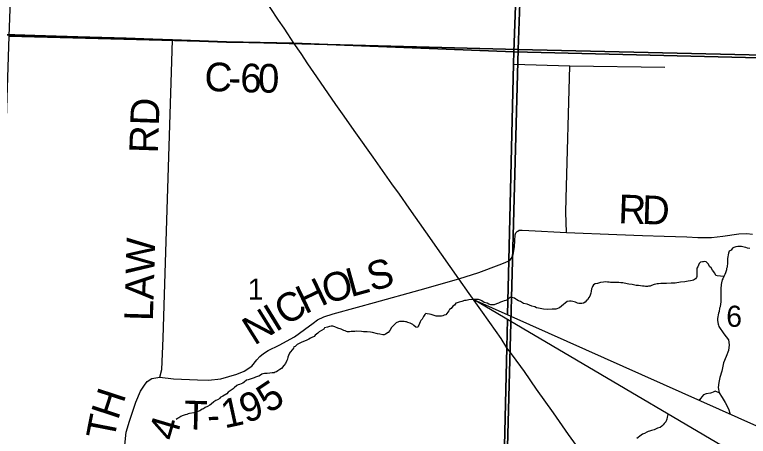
# Model space of a CAD drawing. Extents: x 0 to 34, y 0 to 22.
# Drawn here: x 4.391 to 5.846, y 16.765 to 17.601 of the extents above; entities that cross this region are included whole.
import ezdxf

# ---------------------------------------------------------------- set-up
doc = ezdxf.new("R2010")
doc.units = 0
for name, color, linetype in [('Default', 7, 'Continuous'), ('GM_X_County_Road', 7, 'Continuous'), ('GM_X_County_Road_Text', 7, 'Continuous'), ('GM_X_Minor_River', 7, 'Continuous'), ('GM_X_Section', 7, 'Continuous'), ('GM_X_Section_Text', 7, 'Continuous'), ('GM_X_Township_Road', 7, 'Continuous'), ('GM_X_Township_Road_Text', 7, 'Continuous'), ('GM_X_US_Route', 7, 'Continuous'), ('SH_Text', 7, 'Continuous')]:
    doc.layers.add(name, color=color, linetype=linetype)

msp = doc.modelspace()

# ---------------------------------------------------------------- linework, layer by layer
at = {"layer": 'Default'}
for points in [[(4.3711, 17.5613), (4.4307, 17.5594), (4.5164, 17.557), (4.6117, 17.5539), (4.6648, 17.552), (4.7035, 17.5507), (4.8106, 17.547), (4.9443, 17.5446), (5.3804, 17.5273), (5.4479, 19.3941), (5.4543, 19.5706), (5.4607, 19.86), (5.4688, 20.2302), (5.4689, 20.2361), (2, 20.2361)], [(5.3682, 17.0062), (5.3707, 17.1134), (5.3798, 17.5031), (5.3804, 17.5273), (4.9443, 17.5446), (4.8106, 17.547), (4.7035, 17.5507), (4.6648, 17.552), (4.6117, 17.5539), (4.5164, 17.557), (4.4307, 17.5594), (4.3711, 17.5613)], [(8.8, 13.4361), (8.8, 17.4621), (8.6626, 17.4644), (8.5283, 17.4669), (8.3778, 17.4688), (7.3975, 17.4842), (6.4218, 17.5004), (6.3799, 17.5028), (5.3804, 17.5273), (5.3798, 17.5031), (5.3707, 17.1134), (5.3682, 17.0062)], [(5.3679, 16.9967), (5.3666, 16.941), (5.3568, 16.5234), (5.3489, 15.9414), (5.3456, 15.8536), (5.3407, 15.722), (5.3386, 15.6646)], [(5.3386, 15.6646), (5.3407, 15.722), (5.3456, 15.8536), (5.3489, 15.9414), (5.3568, 16.5234), (5.3666, 16.941), (5.3679, 16.9967)]]:
    msp.add_lwpolyline(points, dxfattribs=at)
msp.add_lwpolyline([(8.8, 17.4621), (8.8, 20.2361), (5.4689, 20.2361), (5.4688, 20.2302), (5.4607, 19.86), (5.4543, 19.5706), (5.4479, 19.3941), (5.3804, 17.5273), (6.3799, 17.5028), (6.4218, 17.5004), (7.3975, 17.4842), (8.3778, 17.4688), (8.5283, 17.4669), (8.6626, 17.4644)], close=True, dxfattribs=at)
at = {"layer": 'GM_X_County_Road'}
for points in [[(4.6008, 16.339), (4.609, 16.551), (4.6097, 16.6991), (4.6094, 16.7478), (4.6122, 16.7735), (4.6186, 16.7955), (4.6308, 16.8329), (4.6404, 16.8545), (4.6484, 16.8669), (4.6536, 16.8737), (4.6626, 16.8795), (4.6788, 16.8827), (4.6826, 16.8976), (4.6855, 16.9599), (4.6881, 17.0461), (4.7038, 17.5502)], [(4.7038, 17.5502), (4.8108, 17.5465), (4.9445, 17.5441)]]:
    msp.add_lwpolyline(points, dxfattribs=at)
at = {"layer": 'GM_X_Minor_River'}
for points in [[(5.8487, 17.1374), (5.8437, 17.1383), (5.8407, 17.1392), (5.8373, 17.14), (5.832, 17.1413), (5.8244, 17.1415), (5.8206, 17.1408), (5.8171, 17.1394), (5.8144, 17.1379), (5.8113, 17.1342), (5.8078, 17.1324), (5.8062, 17.1279), (5.8045, 17.1173), (5.804, 17.1135), (5.8043, 17.1093), (5.8042, 17.1063), (5.8038, 17.104), (5.8033, 17.1002), (5.8025, 17.0976), (5.8024, 17.0949), (5.8004, 17.0893), (5.7992, 17.0862), (5.7972, 17.0817), (5.7952, 17.0776), (5.7936, 17.075), (5.7923, 17.0697), (5.7915, 17.0663), (5.7909, 17.0572), (5.7912, 17.0526), (5.7911, 17.0492), (5.7907, 17.031), (5.7902, 17.028), (5.7897, 17.0219), (5.7885, 17.0189), (5.788, 17.0128), (5.7867, 17.0091), (5.7846, 16.9985), (5.7841, 16.9951), (5.7852, 16.9905), (5.7855, 16.9878), (5.7862, 16.9852)], [(5.7972, 17.0817), (5.7835, 17.0832), (5.7809, 17.084), (5.7791, 17.0883), (5.7743, 17.0948), (5.7717, 17.0991), (5.7695, 17.1014), (5.7658, 17.1072), (5.7621, 17.1107), (5.7591, 17.1116), (5.7568, 17.1112), (5.7545, 17.1109), (5.751, 17.1102), (5.7483, 17.1076), (5.7464, 17.1047), (5.7451, 17.1013), (5.7435, 17.0983), (5.7432, 17.0819), (5.7427, 17.0797), (5.7408, 17.0771), (5.7369, 17.0749), (5.7342, 17.0742), (5.7308, 17.0735), (5.7262, 17.0729), (5.7197, 17.0711), (5.7113, 17.0706), (5.7006, 17.0686), (5.6923, 17.0684), (5.6835, 17.0682), (5.6778, 17.068), (5.6721, 17.0681), (5.6675, 17.0675), (5.6649, 17.0672), (5.6622, 17.0665), (5.6591, 17.0662), (5.6534, 17.064), (5.6507, 17.063), (5.6476, 17.0627), (5.6454, 17.0623), (5.6416, 17.0624), (5.6389, 17.0629), (5.6355, 17.063), (5.6317, 17.0634), (5.6275, 17.0639), (5.623, 17.0644), (5.615, 17.0661), (5.6089, 17.0667), (5.6055, 17.0675), (5.6025, 17.068), (5.5995, 17.0688), (5.5965, 17.0692), (5.5927, 17.0697), (5.5889, 17.0698), (5.5725, 17.0702), (5.5699, 17.0707), (5.5661, 17.0708), (5.563, 17.0712), (5.5585, 17.0709), (5.5527, 17.0703), (5.5462, 17.0682), (5.5416, 17.0676), (5.5386, 17.0657), (5.5366, 17.0624), (5.5358, 17.0601), (5.5349, 17.0575), (5.5341, 17.0526), (5.5332, 17.0488), (5.5312, 17.0431), (5.5292, 17.0405), (5.5268, 17.036), (5.5245, 17.0342), (5.5222, 17.0312), (5.5187, 17.0294), (5.5153, 17.0283), (5.5096, 17.0285), (5.5065, 17.0293), (5.5028, 17.0309), (5.5005, 17.0317), (5.4975, 17.0326), (5.4944, 17.033), (5.4907, 17.0331), (5.4864, 17.0321), (5.4748, 17.0229), (5.4709, 17.0196), (5.464, 17.0175), (5.4564, 17.0169), (5.4469, 17.0167), (5.4393, 17.0169), (5.4325, 17.0186), (5.4295, 17.0191), (5.4257, 17.0199), (5.4223, 17.0215), (5.4163, 17.0232), (5.4068, 17.0269), (5.4, 17.0285), (5.3936, 17.0321), (5.3899, 17.0337)], [(5.3899, 17.0337), (5.3865, 17.0357), (5.3843, 17.0373), (5.382, 17.0392), (5.3771, 17.0405), (5.3725, 17.0402), (5.3694, 17.0373), (5.3648, 17.0347), (5.3614, 17.0337), (5.3579, 17.0323), (5.3544, 17.0308), (5.3502, 17.029), (5.3464, 17.0276), (5.3414, 17.0258), (5.338, 17.0259), (5.3353, 17.0256), (5.3308, 17.0268), (5.3274, 17.0288), (5.3217, 17.0305), (5.3169, 17.0336), (5.3142, 17.0352), (5.3108, 17.0361), (5.2994, 17.0364), (5.2914, 17.0354), (5.2861, 17.0344), (5.283, 17.0341), (5.2777, 17.0327), (5.2746, 17.032), (5.2723, 17.031), (5.2681, 17.0299), (5.2658, 17.0292), (5.2627, 17.0251), (5.2596, 17.0229), (5.2561, 17.0188), (5.2533, 17.0166), (5.2514, 17.014), (5.2498, 17.011), (5.2478, 17.0088), (5.2455, 17.0062), (5.2424, 17.0051), (5.2397, 17.004), (5.2371, 17.0033), (5.2313, 17.0031), (5.2264, 17.0036), (5.2226, 17.0045), (5.2166, 17.0065), (5.2136, 17.0073), (5.2086, 17.0082), (5.2064, 17.0083), (5.204, 17.0064), (5.2017, 17.0027), (5.1985, 16.9971), (5.1962, 16.9945), (5.195, 16.9919), (5.1934, 16.9889), (5.1925, 16.9858), (5.191, 16.9832), (5.1894, 16.981), (5.1864, 16.9818), (5.1826, 16.9849), (5.1804, 16.9869), (5.1751, 16.9897), (5.1702, 16.991), (5.168, 16.9918), (5.1657, 16.9922), (5.163, 16.9927), (5.1596, 16.9927), (5.1566, 16.9928), (5.1539, 16.9929), (5.1516, 16.9922), (5.1474, 16.99), (5.1447, 16.9878), (5.14, 16.983), (5.1377, 16.9808), (5.1349, 16.9747), (5.1317, 16.971), (5.1263, 16.9674), (5.1233, 16.9663), (5.1206, 16.9664), (5.1149, 16.9676), (5.1104, 16.9685), (5.1005, 16.971), (5.0964, 16.9715), (5.0895, 16.9725), (5.0827, 16.9726), (5.0785, 16.9731), (5.0694, 16.9733), (5.0652, 16.9731), (5.0618, 16.9731), (5.058, 16.9729), (5.0549, 16.9726), (5.0511, 16.9726), (5.0489, 16.9731), (5.0459, 16.9743), (5.0436, 16.9751), (5.0383, 16.9775), (5.0319, 16.9796), (5.0259, 16.982), (5.0214, 16.9836), (5.0187, 16.9837), (5.0149, 16.983)], [(5.0149, 16.983), (5.0114, 16.9816), (5.0053, 16.9799), (5.0037, 16.9776), (4.9948, 16.9721), (4.9918, 16.9699), (4.9867, 16.9659), (4.9844, 16.9629), (4.9801, 16.9611), (4.9774, 16.96), (4.974, 16.9575), (4.9686, 16.9549), (4.9636, 16.9528), (4.959, 16.951), (4.9536, 16.9485), (4.9513, 16.947), (4.947, 16.9433), (4.9443, 16.9426), (4.9435, 16.94), (4.9419, 16.937), (4.9373, 16.9322), (4.9357, 16.9299), (4.9341, 16.9254), (4.9325, 16.922), (4.9316, 16.9179), (4.9304, 16.9156), (4.9276, 16.9096), (4.9245, 16.9055), (4.9201, 16.8996), (4.9163, 16.8978), (4.9128, 16.8952), (4.9101, 16.893), (4.9074, 16.8923), (4.9051, 16.8912), (4.9017, 16.8909), (4.8967, 16.8906), (4.8918, 16.89), (4.8865, 16.8898), (4.883, 16.8891), (4.8807, 16.8884), (4.878, 16.8862), (4.8753, 16.8847), (4.8726, 16.8836), (4.8684, 16.8822), (4.8657, 16.8812), (4.8619, 16.8801), (4.8557, 16.8776), (4.8535, 16.8773), (4.8504, 16.8762), (4.8461, 16.8725), (4.843, 16.8703), (4.8365, 16.8678), (4.8342, 16.8675), (4.8311, 16.8657), (4.8261, 16.8613), (4.8238, 16.8594), (4.8203, 16.8568), (4.8145, 16.8528), (4.8114, 16.8495), (4.8033, 16.8447), (4.7986, 16.8422), (4.7978, 16.8399), (4.7928, 16.8374), (4.7894, 16.8363), (4.7855, 16.8338), (4.7805, 16.829), (4.7781, 16.8271), (4.7735, 16.8246), (4.7689, 16.8224), (4.765, 16.8199), (4.7627, 16.8188), (4.76, 16.8173), (4.7577, 16.8159), (4.7539, 16.8144), (4.7458, 16.812), (4.7374, 16.8103), (4.7351, 16.81), (4.7321, 16.8085), (4.7286, 16.8078), (4.7252, 16.8068), (4.7229, 16.8057), (4.7202, 16.8043), (4.7163, 16.8017), (4.714, 16.8006), (4.7113, 16.7984)], [(5.7862, 16.9852), (5.7868, 16.9827), (5.7968, 16.9681), (5.8061, 16.9566), (5.8078, 16.9463), (5.8065, 16.9353), (5.8013, 16.9232), (5.7966, 16.9108), (5.7932, 16.8941), (5.7892, 16.8821), (5.7871, 16.8718), (5.7858, 16.862), (5.7879, 16.8517), (5.7934, 16.8421), (5.7997, 16.8321), (5.8059, 16.8199), (5.8096, 16.8091)], [(5.7879, 16.8517), (5.7797, 16.8546), (5.7759, 16.8525), (5.7728, 16.8514), (5.7705, 16.8507), (5.7621, 16.8494), (5.7567, 16.8472), (5.7536, 16.8435), (5.7493, 16.8383), (5.7475, 16.8368)], [(5.6859, 16.8096), (5.6859, 16.8083), (5.6846, 16.8031), (5.6841, 16.7989), (5.6817, 16.794), (5.6786, 16.7907), (5.6766, 16.7881), (5.6739, 16.7855), (5.6704, 16.7829), (5.6655, 16.7811), (5.6616, 16.7793), (5.6585, 16.7783), (5.6536, 16.7765), (5.6497, 16.7754), (5.6471, 16.7747), (5.6444, 16.7733), (5.6397, 16.7707), (5.6355, 16.7693), (5.6328, 16.7675), (5.6247, 16.7612)]]:
    msp.add_lwpolyline(points, dxfattribs=at)
at = {"layer": 'GM_X_Section'}
for points in [[(4.4175, 18.5694), (5.4246, 18.5313), (5.3894, 17.5316), (4.38, 17.558)], [(5.4246, 18.5313), (6.3991, 18.5175), (6.392, 17.5084), (5.3894, 17.5316)], [(4.38, 17.558), (5.3894, 17.5316), (5.3619, 16.5226), (4.3467, 16.5583)], [(5.3894, 17.5316), (6.392, 17.5084), (6.4295, 17.5071), (6.4046, 16.4989), (5.3619, 16.5226)]]:
    msp.add_lwpolyline(points, close=True, dxfattribs=at)
at = {"layer": 'GM_X_Township_Road'}
for points in [[(3.5035, 17.5989), (3.5046, 17.5908), (3.5078, 17.5878), (3.5151, 17.5861), (3.5267, 17.5856), (3.5882, 17.5838), (3.6682, 17.5814), (3.8116, 17.5772), (3.8973, 17.5747), (4.015, 17.5713), (4.0648, 17.5694), (4.1543, 17.5676), (4.2958, 17.5631), (4.3713, 17.5608), (4.431, 17.5589), (4.5166, 17.5564), (4.612, 17.5534), (4.665, 17.5515), (4.7038, 17.5502)], [(5.3801, 17.5026), (5.4914, 17.4991), (5.6801, 17.4969)], [(5.4851, 17.1691), (5.484, 17.2097), (5.4845, 17.2364), (5.4914, 17.4991)], [(5.3732, 17.1151), (5.3762, 17.1181), (5.3795, 17.1253), (5.3822, 17.1405), (5.3829, 17.1643), (5.3844, 17.1684), (5.3869, 17.1708)], [(5.3869, 17.1708), (5.3882, 17.172), (5.391, 17.1735), (5.3971, 17.1738), (5.4104, 17.1733), (5.4851, 17.1691), (5.585, 17.1652), (5.6355, 17.1633), (5.6787, 17.1618), (5.7239, 17.1607), (5.7454, 17.159), (5.7726, 17.1589), (5.7948, 17.1618), (5.8268, 17.1662), (5.8426, 17.1673), (5.8537, 17.1656)], [(5.2715, 17.0773), (5.3109, 17.0899), (5.3515, 17.1052), (5.3637, 17.1097), (5.3709, 17.1129), (5.3732, 17.1151)], [(4.6788, 16.8827), (4.7055, 16.8789), (4.7537, 16.8769), (4.7755, 16.8766), (4.7994, 16.8792), (4.8315, 16.8881), (4.8462, 16.8945), (4.8611, 16.9044), (4.871, 16.9166), (4.8771, 16.9236), (4.8841, 16.9293), (4.8934, 16.9352), (4.9151, 16.9461), (4.9455, 16.9626), (4.9652, 16.9766), (4.9824, 16.9894), (4.9912, 16.9958), (5.0039, 17.002), (5.0223, 17.0078), (5.0707, 17.0211), (5.1046, 17.0302), (5.1951, 17.0556), (5.2715, 17.0773)]]:
    msp.add_lwpolyline(points, dxfattribs=at)
at = {"layer": 'GM_X_US_Route'}
for points in [[(4.9445, 17.5441), (4.9327, 17.5628), (4.9251, 17.5737), (4.9143, 17.59), (4.8972, 17.6151), (4.8626, 17.6672), (4.8311, 17.7133), (4.8044, 17.7531), (4.7917, 17.7715), (4.7641, 17.8117), (4.731, 17.861), (4.7065, 17.8991), (4.673, 17.9468), (4.6468, 17.9863), (4.6169, 18.0299), (4.6138, 18.0345), (4.6122, 18.0369)], [(5.0409, 17.4042), (5.0277, 17.423), (4.9897, 17.4779), (4.9724, 17.5035), (4.9592, 17.5237), (4.9445, 17.5441)], [(5.2715, 17.0773), (5.2372, 17.1261), (5.2064, 17.1702), (5.173, 17.2176), (5.1536, 17.2452), (5.1386, 17.2657), (5.1016, 17.3181), (5.0673, 17.3664), (5.0409, 17.4042)], [(5.5186, 16.7276), (5.4892, 16.7689), (5.4589, 16.8121), (5.4258, 16.8586), (5.4014, 16.8934), (5.378, 16.9258), (5.3669, 16.9404), (5.3553, 16.9593), (5.3329, 16.9905), (5.3151, 17.0157), (5.2922, 17.0484), (5.2715, 17.0773)]]:
    msp.add_lwpolyline(points, dxfattribs=at)
at = {"layer": 'SH_Text'}
msp.add_lwpolyline([(6.0096, 16.9213), (7.8264, 16.9213), (7.8264, 16.5183), (6.0096, 16.5183), (6.0096, 16.619), (5.3006, 17.0363), (6.0096, 16.7198)], close=True, dxfattribs=at)

# ---------------------------------------------------------------- texts
at = {"layer": 'GM_X_County_Road_Text'}
for s, height, rotation, p in [('C', 0.0568, 357.1145, (4.766, 17.4503)), ('6', 0.0568, 358.8967, (4.8378, 17.4472)), ('0', 0.0568, 359.0403, (4.873, 17.4466)), ('-', 0.0568, 358.4251, (4.814, 17.4479)), ('RD', 0.05682, 88.0252, (4.6748, 17.3254)), ('LAW', 0.05682, 88.2825, (4.6648, 16.9931)), ('H', 0.0568, 71.9043, (4.5956, 16.7959)), ('T', 0.0568, 78.9607, (4.5879, 16.7559)), ('4', 0.0568, 73.4817, (4.7097, 16.7537))]:
    msp.add_text(s, height=height, rotation=rotation, dxfattribs=at).set_placement(p)
at = {"layer": 'GM_X_Section_Text'}
for s, p in [('1', (4.853, 17.036)), ('6', (5.8018, 16.9822))]:
    msp.add_text(s, height=0.0419, rotation=0, dxfattribs=at).set_placement(p)
at = {"layer": 'GM_X_Township_Road_Text'}
for s, rotation, p in [('R', 357.9388, (5.5871, 17.1878)), ('D', 358.1536, (5.634, 17.1861)), ('S', 15.3793, (5.0983, 17.0521)), ('O', 15.6955, (5.0093, 17.0273)), ('L', 15.3764, (5.0573, 17.0408)), ('H', 25.6641, (4.9666, 17.0066)), ('C', 31.4303, (4.9281, 16.983)), ('I', 31.4986, (4.9083, 16.9708)), ('N', 32.0996, (4.866, 16.9443)), ('5', 33.7131, (4.8952, 16.8094)), ('9', 20.3289, (4.8495, 16.7906)), ('T', 358.3412, (4.7262, 16.7794)), ('1', 12.2852, (4.807, 16.7807)), ('-', 2.853, (4.7736, 16.7782))]:
    msp.add_text(s, height=0.0568, rotation=rotation, dxfattribs=at).set_placement(p)

doc.saveas('drawing.dxf')
